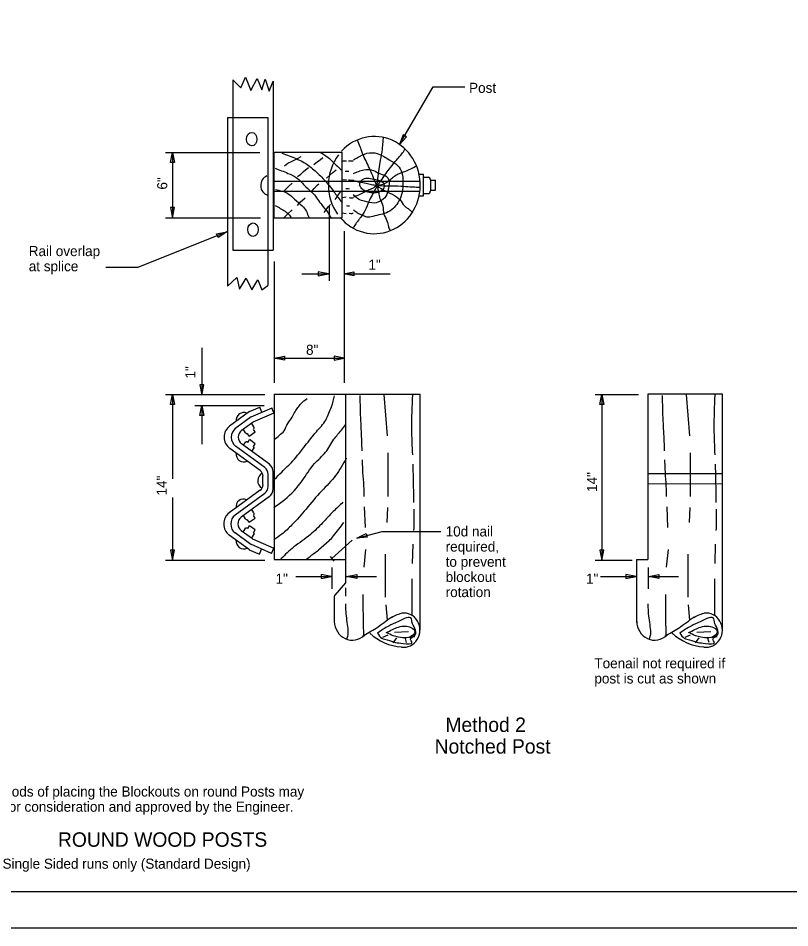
# Model space of a CAD drawing. Extents: x 0 to 34, y 0 to 22.
# Drawn here: x 8.69 to 19.37, y 0 to 12.6 of the extents above; entities that cross this region are included whole.
import ezdxf

# ---------------------------------------------------------------- set-up
doc = ezdxf.new("R2010")
doc.units = 0
for name, color, linetype in [('SH_Border', 7, 'Continuous'), ('SH_Cut_Line', 7, 'Continuous'), ('ST_Details', 7, 'Continuous'), ('ST_Text', 7, 'Continuous')]:
    doc.layers.add(name, color=color, linetype=linetype)

msp = doc.modelspace()

# ---------------------------------------------------------------- linework, layer by layer
at = {"layer": 'SH_Border'}
msp.add_lwpolyline([(2, 21.5), (33.5, 21.5), (33.5, 0.5), (2, 0.5)], close=True, dxfattribs=at)
at = {"layer": 'SH_Cut_Line'}
msp.add_lwpolyline([(0, 0), (34, 0), (34, 22), (0, 22)], close=True, dxfattribs=at)
at = {"layer": 'ST_Details'}
for p, q in [((11.658, 11.741), (11.658, 11.227)), ((12.218, 11.721), (12.218, 9.383)), ((11.583, 11.221), (11.583, 8.885)), ((11.583, 11.221), (12.143, 11.221)), ((11.658, 11.221), (11.658, 9.383)), ((12.143, 11.221), (12.143, 8.895)), ((12.232, 10.739), (13.171, 10.739)), ((12.232, 9.829), (12.232, 10.739)), ((13.17, 9.829), (13.17, 10.739)), ((13.216, 10.476), (13.266, 10.478)), ((12.225, 10.339), (14.248, 10.339)), ((13.174, 10.357), (13.23, 10.361)), ((14.239, 10.437), (14.299, 10.437)), ((14.251, 10.342), (14.251, 10.342)), ((14.299, 10.136), (14.299, 10.437)), ((14.299, 10.394), (14.367, 10.394)), ((14.393, 10.36), (14.394, 10.206)), ((14.393, 10.353), (14.464, 10.353)), ((14.464, 10.213), (14.464, 10.353)), ((14.394, 10.213), (14.464, 10.213)), ((12.225, 10.2), (14.248, 10.2)), ((13.174, 10.111), (13.228, 10.12)), ((14.239, 10.136), (14.299, 10.136)), ((14.299, 10.17), (14.358, 10.17)), ((12.232, 9.829), (13.17, 9.829)), ((13.17, 9.899), (13.226, 9.892)), ((11.658, 9.383), (12.143, 9.383)), ((12.143, 9.383), (12.218, 9.383)), ((12.232, 7.389), (12.232, 5.099)), ((12.232, 7.389), (14.252, 7.389)), ((13.218, 7.389), (13.218, 4.777)), ((13.748, 7.383), (13.795, 6.81)), ((14.252, 4.122), (14.252, 7.389)), ((17.405, 7.389), (17.405, 5.099)), ((18.439, 7.389), (17.405, 7.389)), ((17.935, 7.383), (17.982, 6.81)), ((18.439, 4.122), (18.439, 7.389)), ((11.887, 7.147), (12.031, 7.21)), ((11.912, 7.074), (12.201, 7.201)), ((12.059, 7.14), (12.031, 7.209)), ((12.227, 7.13), (12.2, 7.2)), ((11.887, 7.147), (11.614, 6.947)), ((11.914, 7.076), (11.684, 6.907)), ((11.941, 7.004), (12.231, 7.13)), ((11.94, 7.003), (11.773, 6.881)), ((11.951, 6.936), (11.921, 6.984)), ((11.835, 6.854), (11.806, 6.9)), ((11.884, 6.807), (11.861, 6.844)), ((11.884, 6.808), (11.966, 6.866)), ((11.966, 6.866), (11.943, 6.902)), ((12.164, 6.42), (11.78, 6.7)), ((11.805, 6.681), (11.837, 6.731)), ((11.865, 6.722), (11.89, 6.76)), ((11.969, 6.703), (11.89, 6.76)), ((11.944, 6.664), (11.968, 6.702)), ((12.038, 6.33), (11.615, 6.638)), ((12.101, 6.375), (11.697, 6.669)), ((11.923, 6.595), (11.954, 6.644)), ((13.803, 6.577), (13.803, 5.972)), ((17.989, 6.577), (17.989, 5.972)), ((12.218, 6.079), (12.218, 6.312)), ((12.076, 6.138), (12.076, 6.253)), ((12.147, 6.109), (12.147, 6.282)), ((12.147, 6.19), (12.147, 6.201)), ((17.405, 6.29), (18.44, 6.293)), ((12.038, 6.061), (11.608, 5.746)), ((17.405, 6.149), (18.439, 6.152)), ((12.101, 6.016), (11.69, 5.715)), ((12.165, 5.971), (11.773, 5.684)), ((13.479, 5.83), (13.492, 5.542)), ((13.798, 5.822), (13.789, 5.613)), ((17.666, 5.83), (17.678, 5.542)), ((17.984, 5.822), (17.975, 5.613)), ((11.835, 5.661), (11.806, 5.707)), ((11.884, 5.615), (11.966, 5.674)), ((11.951, 5.744), (11.921, 5.791)), ((11.966, 5.674), (11.943, 5.709)), ((11.884, 5.615), (11.861, 5.651)), ((11.865, 5.529), (11.89, 5.568)), ((11.969, 5.51), (11.89, 5.567)), ((11.888, 5.233), (11.608, 5.437)), ((11.908, 5.309), (11.691, 5.468)), ((11.931, 5.384), (11.773, 5.499)), ((11.805, 5.489), (11.837, 5.539)), ((11.923, 5.402), (11.954, 5.451)), ((11.944, 5.471), (11.968, 5.509)), ((12.196, 5.184), (11.907, 5.31)), ((11.931, 5.385), (12.224, 5.257)), ((12.629, 5.363), (12.629, 5.363)), ((12.994, 5.358), (12.846, 5.231)), ((13.029, 5.113), (13.309, 5.367)), ((14.151, 5.312), (14.143, 5.046)), ((18.338, 5.312), (18.33, 5.046)), ((11.885, 5.234), (12.029, 5.172)), ((12.028, 5.172), (12.057, 5.244)), ((12.195, 5.184), (12.224, 5.257)), ((13.497, 5.237), (13.472, 4.995)), ((13.769, 5.175), (13.769, 4.578)), ((17.684, 5.237), (17.659, 4.995)), ((17.956, 5.175), (17.956, 4.578)), ((12.232, 5.099), (13.224, 5.099)), ((13.06, 5.079), (13.009, 5.14)), ((17.25, 4.307), (17.25, 5.099)), ((17.25, 5.099), (17.405, 5.099)), ((13.218, 4.777), (13.07, 4.606)), ((13.218, 4.706), (13.218, 4.592)), ((13.064, 4.307), (13.064, 4.594)), ((13.07, 4.599), (13.07, 4.606)), ((13.776, 4.472), (13.796, 4.258)), ((17.963, 4.472), (17.983, 4.258)), ((13.064, 4.229), (13.064, 4.307)), ((17.25, 4.229), (17.25, 4.307)), ((13.736, 4.023), (13.81, 4.058)), ((13.897, 4.094), (14.092, 4.101)), ((14.179, 4.108), (14.173, 4.143)), ((17.922, 4.023), (17.996, 4.058)), ((18.083, 4.094), (18.278, 4.101)), ((18.366, 4.108), (18.36, 4.143)), ((13.877, 3.945), (13.93, 4.016)), ((14.065, 3.952), (14.045, 4.023)), ((14.18, 4.029), (14.099, 4.022)), ((14.099, 4.022), (14.139, 4.023)), ((18.063, 3.945), (18.117, 4.016)), ((18.251, 3.952), (18.231, 4.023)), ((18.366, 4.029), (18.286, 4.022)), ((18.286, 4.022), (18.325, 4.023))]:
    msp.add_line(p, q, dxfattribs=at)
for points in [[(11.658, 11.741), (11.77, 11.632), (11.836, 11.78), (11.91, 11.592), (11.994, 11.76), (12.06, 11.602), (12.106, 11.751), (12.162, 11.583), (12.218, 11.721)], [(12.372, 10.549), (12.418, 10.586), (12.478, 10.617), (12.552, 10.651), (12.604, 10.679)], [(12.779, 10.571), (12.833, 10.611), (12.867, 10.635), (12.904, 10.668)], [(12.556, 10.401), (12.598, 10.436), (12.635, 10.474), (12.687, 10.516), (12.708, 10.527)], [(12.955, 10.381), (12.998, 10.416), (13.042, 10.458), (13.088, 10.496)], [(12.37, 10.206), (12.397, 10.231), (12.435, 10.27), (12.478, 10.31)], [(12.752, 10.2), (12.783, 10.239), (12.825, 10.281), (12.85, 10.301)], [(12.552, 10.003), (12.593, 10.049), (12.658, 10.109)], [(13.076, 10.085), (13.103, 10.12), (13.126, 10.16), (13.153, 10.197)], [(12.923, 9.906), (12.952, 9.943), (12.978, 9.981), (13.009, 10.016)], [(12.359, 9.826), (12.422, 9.888), (12.478, 9.941)], [(11.583, 8.885), (11.714, 9.003), (11.752, 8.845), (11.845, 8.994), (11.92, 8.835), (12.004, 8.974), (12.06, 8.835), (12.143, 8.895)]]:
    msp.add_lwpolyline(points, dxfattribs=at)
for centre in [(11.92, 10.921), (11.938, 9.668)]:
    msp.add_ellipse(centre, major_axis=(0.0005, 0.0936), ratio=0.773782, dxfattribs=at)
for centre, major_axis, start_param, end_param in [((13.618, 10.284), (0, 0.673), 2.303639, 7.079119), ((13.618, 10.284), (0, 0.673), 0.900881, 2.214399), ((12.178, 10.279), (0, -0.141), 3.514867, 5.984065), ((14.364, 10.364), (0, 0.03), 4.574534, 6.237266), ((14.366, 10.365), (0, -0.0298), 1.431351, 1.439211), ((14.363, 10.201), (0, -0.0326), 6.093782, 8.002272), ((11.807, 7.028), (0, -0.107), 2.687211, 4.851441), ((11.715, 6.793), (0, -0.187), 3.747084, 5.680264), ((11.935, 6.924), (0, 0.0198), 3.70437, 5.352473), ((11.778, 6.793), (0, -0.15), 3.747137, 5.680324), ((11.84, 6.793), (0, -0.112), 3.747102, 5.680297), ((11.848, 6.865), (0, -0.0195), 5.247458, 6.879592), ((11.85, 6.708), (0, 0.021), 5.452301, 7.118326), ((11.81, 6.565), (0, -0.115), 4.640651, 6.714317), ((11.935, 6.646), (0, 0.021), 4.196406, 5.73538), ((11.988, 6.253), (0, 0.0937), 4.712389, 5.680377), ((12.041, 6.282), (0, 0.112), 4.712389, 5.68034), ((12.094, 6.312), (0, 0.131), 4.712389, 5.680267), ((12.117, 6.189), (0, -0.12), 3.613765, 5.74142), ((11.988, 6.138), (0, -0.0937), 0.605563, 1.570796), ((12.041, 6.109), (0, -0.112), 0.605651, 1.570796), ((12.094, 6.079), (0, -0.131), 0.605566, 1.570796), ((11.804, 5.831), (0, -0.107), 2.687211, 4.851441), ((11.709, 5.592), (0, -0.187), 3.747091, 5.68028), ((11.771, 5.592), (0, -0.15), 3.747115, 5.680355), ((11.833, 5.592), (0, -0.112), 3.747102, 5.680258), ((11.935, 5.731), (0, 0.0198), 3.70437, 5.352473), ((11.848, 5.672), (0, -0.0195), 5.247458, 6.879592), ((11.85, 5.515), (0, 0.021), 5.452301, 7.118326), ((11.935, 5.453), (0, 0.021), 4.196406, 5.73538), ((11.81, 5.362), (0, -0.115), 4.640651, 6.714317), ((14.097, 3.856), (0, 0.508), 0.179437, 0.530353), ((14.025, 4.122), (0, 0.237), 2.997307, 6.40595), ((18.284, 3.856), (0, 0.508), 0.179437, 0.530353), ((18.212, 4.122), (0, 0.237), 2.997307, 6.40595), ((13.313, 4.247), (0, -0.264), 4.726587, 7.018323), ((17.5, 4.247), (0, -0.264), 4.726587, 7.018323), ((14.039, 4.667), (0, -0.78), 5.564047, 6.222034), ((18.226, 4.667), (0, -0.78), 5.564047, 6.222034)]:
    msp.add_ellipse(centre, major_axis=major_axis, ratio=0.944544, start_param=start_param, end_param=end_param, dxfattribs=at)
for points in [[(13.654, 10.279), (13.617, 10.359), (13.573, 10.465), (13.527, 10.569), (13.479, 10.668), (13.435, 10.777), (13.422, 10.814), (13.385, 10.909)], [(13.656, 10.284), (13.667, 10.374), (13.683, 10.505), (13.704, 10.629), (13.729, 10.781), (13.738, 10.88), (13.744, 10.945)], [(12.337, 10.726), (12.439, 10.688), (12.629, 10.606), (12.779, 10.496), (12.923, 10.357), (13.057, 10.193), (13.153, 10.063), (13.173, 10.038)], [(12.867, 10.739), (12.961, 10.679), (13.09, 10.56), (13.171, 10.488)], [(13.328, 10.633), (13.395, 10.671), (13.514, 10.724), (13.658, 10.721), (13.823, 10.635), (13.942, 10.553), (13.999, 10.456), (14.011, 10.317), (14.003, 10.182), (13.959, 10.065), (13.892, 9.974), (13.811, 9.912), (13.706, 9.877), (13.596, 9.85), (13.514, 9.841), (13.45, 9.868), (13.399, 9.886), (13.349, 9.923), (13.33, 9.937)], [(13.658, 10.281), (13.706, 10.341), (13.777, 10.441), (13.842, 10.529), (13.928, 10.635), (13.972, 10.686), (14.02, 10.746), (14.042, 10.783)], [(13.174, 10.622), (13.224, 10.622), (13.23, 10.622)], [(13.262, 10.621), (13.301, 10.62), (13.326, 10.622)], [(12.243, 10.52), (12.422, 10.447), (12.535, 10.39), (12.671, 10.259), (12.771, 10.166), (12.89, 10.01), (12.973, 9.903), (13.021, 9.835), (13.03, 9.828)], [(13.33, 10.445), (13.397, 10.474), (13.472, 10.494), (13.606, 10.487), (13.702, 10.438), (13.786, 10.405), (13.823, 10.312), (13.813, 10.248), (13.792, 10.153), (13.719, 10.071), (13.614, 10.036), (13.481, 10.06), (13.399, 10.089), (13.351, 10.127), (13.328, 10.153)], [(13.66, 10.279), (13.779, 10.317), (13.898, 10.41), (14.04, 10.474), (14.122, 10.509), (14.201, 10.551)], [(13.262, 10.358), (13.289, 10.354), (13.328, 10.354)], [(13.654, 10.277), (13.577, 10.288), (13.506, 10.306), (13.414, 10.323), (13.356, 10.337), (13.335, 10.343)], [(13.414, 10.277), (13.429, 10.334), (13.462, 10.368), (13.541, 10.381), (13.637, 10.361), (13.733, 10.326), (13.754, 10.266), (13.702, 10.195), (13.631, 10.177), (13.546, 10.182), (13.481, 10.208), (13.437, 10.244), (13.418, 10.277)], [(12.248, 10.222), (12.426, 10.164), (12.512, 10.091), (12.618, 9.996), (12.677, 9.919), (12.712, 9.841), (12.723, 9.826)], [(13.221, 10.237), (13.239, 10.239), (13.268, 10.232)], [(13.66, 10.277), (13.614, 10.197), (13.587, 10.146), (13.539, 10.049), (13.518, 9.996), (13.46, 9.883), (13.439, 9.853), (13.418, 9.828), (13.389, 9.786), (13.36, 9.749), (13.341, 9.718), (13.328, 9.698), (13.322, 9.693)], [(13.654, 10.279), (13.61, 10.248), (13.543, 10.217), (13.435, 10.164), (13.358, 10.129), (13.328, 10.118)], [(13.654, 10.277), (13.769, 10.204), (13.898, 10.14), (13.988, 10.06), (14.053, 9.979), (14.095, 9.952), (14.132, 9.919), (14.149, 9.91)], [(13.658, 10.277), (13.827, 10.275), (13.984, 10.27), (14.114, 10.261), (14.199, 10.257), (14.249, 10.253)], [(13.658, 10.277), (13.673, 10.182), (13.696, 10.098), (13.733, 9.998), (13.75, 9.883), (13.792, 9.788), (13.815, 9.707), (13.836, 9.649)], [(13.269, 10.111), (13.27, 10.111), (13.32, 10.109), (13.326, 10.111)], [(12.246, 10), (12.382, 9.921), (12.433, 9.879), (12.468, 9.828)], [(13.232, 10.002), (13.257, 9.996), (13.274, 9.998)], [(13.27, 9.897), (13.31, 9.892), (13.324, 9.895)], [(12.233, 6.758), (12.302, 6.819), (12.368, 6.881), (12.419, 6.984), (12.48, 7.069), (12.52, 7.146), (12.56, 7.204), (12.604, 7.261), (12.687, 7.327)], [(12.237, 6.211), (12.335, 6.311), (12.488, 6.465), (12.662, 6.677), (12.815, 6.869), (12.945, 7.031), (12.989, 7.127), (13.025, 7.215), (13.068, 7.368)], [(13.416, 7.37), (13.427, 7.018), (13.44, 6.733), (13.444, 6.606)], [(14.144, 7.378), (14.132, 6.911), (14.144, 6.548)], [(17.602, 7.37), (17.613, 7.018), (17.627, 6.733), (17.631, 6.606)], [(18.33, 7.378), (18.319, 6.911), (18.331, 6.548)], [(12.226, 5.819), (12.379, 5.931), (12.618, 6.188), (12.789, 6.427), (12.942, 6.585), (13.058, 6.765), (13.163, 6.892), (13.219, 6.966)], [(13.23, 6.504), (13.082, 6.262), (12.887, 6.048), (12.672, 5.799), (12.477, 5.579), (12.336, 5.451), (12.228, 5.372)], [(13.449, 6.478), (13.453, 6.349), (13.474, 5.979), (13.474, 5.972)], [(17.635, 6.478), (17.64, 6.349), (17.66, 5.979), (17.66, 5.972)], [(14.149, 6.42), (14.152, 6.328), (14.161, 5.887)], [(18.336, 6.42), (18.339, 6.328), (18.347, 5.887)], [(13.183, 5.892), (13.048, 5.764), (12.9, 5.607), (12.732, 5.444), (12.504, 5.273), (12.323, 5.108)], [(14.163, 5.795), (14.166, 5.638), (14.161, 5.5)], [(18.349, 5.795), (18.352, 5.638), (18.347, 5.5)], [(12.994, 5.358), (13.051, 5.427), (13.197, 5.611)], [(12.673, 5.1), (12.782, 5.185), (12.846, 5.231)], [(14.139, 4.833), (14.139, 4.62), (14.139, 4.371), (14.139, 4.328)], [(18.326, 4.833), (18.326, 4.62), (18.326, 4.371), (18.326, 4.328)], [(13.46, 4.613), (13.46, 4.443), (13.467, 4.058)], [(17.647, 4.613), (17.647, 4.443), (17.653, 4.058)], [(13.218, 4.485), (13.218, 4.464), (13.238, 4.229), (13.238, 4.009), (13.232, 3.994)], [(17.405, 4.485), (17.405, 4.464), (17.425, 4.229), (17.425, 4.009), (17.418, 3.994)], [(13.453, 4.037), (13.641, 4.151), (13.86, 4.307)], [(13.662, 4.08), (13.816, 4.179), (13.951, 4.243), (14.132, 4.279), (14.139, 4.235), (14.18, 4.143), (14.18, 4.051), (14.119, 3.994), (14.139, 3.952), (14.018, 3.938), (13.91, 3.952), (13.796, 3.987), (13.722, 4.009), (13.662, 4.08)], [(17.64, 4.037), (17.828, 4.151), (18.046, 4.307)], [(17.848, 4.08), (18.003, 4.179), (18.137, 4.243), (18.319, 4.279), (18.326, 4.235), (18.366, 4.143), (18.366, 4.051), (18.306, 3.994), (18.325, 3.952), (18.204, 3.938), (18.097, 3.952), (17.983, 3.987), (17.909, 4.009), (17.848, 4.08)], [(13.783, 4.087), (13.87, 4.13), (13.951, 4.165), (14.045, 4.179), (14.125, 4.158), (14.179, 4.108), (14.152, 4.051), (14.065, 4.016), (13.951, 4.023), (13.877, 4.044), (13.789, 4.087)], [(17.969, 4.087), (18.057, 4.13), (18.137, 4.165), (18.231, 4.179), (18.312, 4.158), (18.366, 4.108), (18.339, 4.051), (18.251, 4.016), (18.137, 4.023), (18.063, 4.044), (17.976, 4.087)]]:
    msp.add_spline(points, degree=3, dxfattribs=at)
at = {"layer": 'ST_Text'}
for p, q in [((10.727, 10.736), (12.033, 10.736)), ((10.822, 10.736), (10.822, 10.159)), ((10.822, 10.159), (10.822, 9.832)), ((12.993, 9.995), (12.993, 8.96)), ((10.727, 9.832), (12.042, 9.832)), ((13.2, 9.644), (13.2, 7.969)), ((12.232, 9.227), (12.232, 7.969)), ((12.616, 9.054), (12.981, 9.054)), ((13.194, 9.054), (13.835, 9.054)), ((11.228, 8.03), (11.228, 7.377)), ((12.232, 7.969), (12.232, 7.544)), ((13.2, 7.969), (13.2, 7.544)), ((12.233, 7.886), (13.2, 7.886)), ((10.727, 7.384), (12.101, 7.384)), ((10.822, 7.384), (10.822, 6.217)), ((16.674, 7.384), (17.274, 7.384)), ((16.769, 7.384), (16.769, 6.217)), ((11.133, 7.234), (12.091, 7.234)), ((11.228, 7.234), (11.228, 6.698)), ((16.769, 6.217), (16.769, 5.959)), ((10.822, 5.959), (10.822, 5.09)), ((16.769, 5.959), (16.769, 5.09)), ((13.376, 5.395), (13.726, 5.488)), ((13.726, 5.488), (14.54, 5.488)), ((10.727, 5.09), (11.826, 5.09)), ((11.826, 5.09), (12.101, 5.09)), ((16.674, 5.09), (16.999, 5.09)), ((16.999, 5.09), (17.188, 5.09)), ((13.028, 4.991), (13.028, 4.694)), ((17.411, 4.991), (17.411, 4.694)), ((12.532, 4.864), (13.021, 4.864)), ((13.234, 4.864), (13.649, 4.864)), ((16.751, 4.864), (17.241, 4.864)), ((17.416, 4.864), (17.83, 4.864))]:
    msp.add_line(p, q, dxfattribs=at)
for points in [[(13.965, 10.848), (14.43, 11.647), (14.87, 11.647)], [(11.575, 9.635), (10.342, 9.145), (9.902, 9.145)]]:
    msp.add_lwpolyline(points, dxfattribs=at)
for points in [[(14.015, 10.982), (13.965, 10.848), (14.063, 10.952)], [(10.794, 10.596), (10.822, 10.736), (10.85, 10.596)], [(10.794, 9.972), (10.822, 9.832), (10.85, 9.972)], [(11.434, 9.611), (11.575, 9.635), (11.454, 9.559)], [(12.841, 9.026), (12.981, 9.054), (12.841, 9.082)], [(13.334, 9.026), (13.194, 9.054), (13.334, 9.082)], [(12.373, 7.858), (12.233, 7.886), (12.373, 7.914)], [(13.06, 7.858), (13.2, 7.886), (13.06, 7.914)], [(11.2, 7.517), (11.228, 7.377), (11.256, 7.517)], [(10.794, 7.244), (10.822, 7.384), (10.85, 7.244)], [(16.741, 7.244), (16.769, 7.384), (16.797, 7.244)], [(11.2, 7.094), (11.228, 7.234), (11.256, 7.094)], [(13.518, 5.407), (13.376, 5.395), (13.503, 5.461)], [(10.794, 5.23), (10.822, 5.09), (10.85, 5.23)], [(16.741, 5.23), (16.769, 5.09), (16.797, 5.23)], [(12.881, 4.836), (13.021, 4.864), (12.881, 4.892)], [(13.374, 4.836), (13.234, 4.864), (13.374, 4.892)], [(17.101, 4.836), (17.241, 4.864), (17.101, 4.892)], [(17.556, 4.836), (17.416, 4.864), (17.556, 4.892)]]:
    msp.add_lwpolyline(points, close=True, dxfattribs=at)

# ---------------------------------------------------------------- texts
for s, rotation, p in [('Post', 360, (14.929, 11.561)), ('6" ', 90, (10.751, 10.222)), ('Rail overlap', 360, (8.833, 9.301)), ('at splice', 360, (8.833, 9.091)), ('1"', 360, (13.536, 9.113)), ('8" ', 360, (12.672, 7.934)), ('1" ', 90, (11.14, 7.606)), ('14" ', 90, (16.702, 6.035)), ('14" ', 90, (10.744, 5.986)), ('10d nail ', 360, (14.605, 5.419)), ('required, ', 360, (14.605, 5.209)), ('to prevent ', 360, (14.605, 4.999)), ('blockout ', 360, (14.605, 4.789)), ('1"', 360, (12.25, 4.764)), ('1" ', 360, (16.548, 4.764)), ('rotation', 360, (14.605, 4.579)), ('Toenail not required if', 360, (16.664, 3.593)), ('post is cut as shown', 360, (16.664, 3.383)), ('Alternate methods of placing the Blockouts on round Posts may', 360, (7.38, 1.817)), ('be submitted for consideration and approved by the Engineer.', 360, (7.38, 1.607)), ('Single Sided runs only (Standard Design)', 360, (8.47, 0.818))]:
    msp.add_text(s, height=0.14, rotation=rotation, dxfattribs=at).set_placement(p)
for s, p in [('  Method 2', (14.452, 2.712)), ('Notched Post', (14.452, 2.412)), ('ROUND WOOD POSTS', (9.237, 1.122))]:
    msp.add_text(s, height=0.2, dxfattribs=at).set_placement(p)

doc.saveas('drawing.dxf')
